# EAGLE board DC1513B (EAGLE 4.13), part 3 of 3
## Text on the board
Top: 4
L2-GND: LAYER 2, GND | 5
Route3: LAYER 3, GND | 6
Bottom: 7
tPlace: PIN A1> | 2
bPlace: 9
tNames: +5.0V | GND | GND | +3.0V | ON | ON | ON | ON | ON | 2/3 | VDD | MIXER | OFF | OFF | SDI | SDQ | OFF | OFF | SDI | SDQ | OFF | MODE | SENSE_I | 1/3 | GND | AMPS | ADC | VIOB | SENSE_B | GND | GND | LTM9004 | DC1513B- | OVDD | 14BIT BIT DIRECT CONVERSION | RECEIVER SUBSYSEM DEMO BOARD | J6 | LO IN | Q OFFSET | I OFFSET | RF IN | (408)432-1900 | WR_EN | www.linear.com | ENCODE | CLOCK
bNames: LTC CONFIDENTIAL | FOR CUSTOMER USE ONLY
tStop: 3
bStop: 8
tCream: 1
bCream: 10
bRestrict: BACK | REV B1
Measures: 2.950 IN | 0.652 | 0.050 IN | 0 | ORIGIN | 0.967 IN | 0.067 IN TOOLING HOLE | 0 | UNPLATED, 2X | 0.050 IN | 3.660 IN | 1.0575
Document: LTM9004 DEMO BOARD | DC1513 | 14BIT BIT DIRECT CONVERSION RCVR SUBSYS | B | 10 | E.TRELEWICZ | 28JSEP09
Reference: A1 | INITIAL RELEASE | 28JAN09 | B1 | VCC3 SUPPLY OPTION | 28SEP09 | 1 | 0.009" | 1 | 0.039" | 1 | 0.009" | 1 | VIEW A | HERE | NO TABS | DC1513 REV B | HERE | NO TABS | HERE | NO TABS | DRILL LEGEND | SYM SIZE QTY TOLERANCE PLTD | .010 | 245 | +0/-.010 | YES | .012 | 70 | +0/- .012 | YES | 994 | .015 | +/- .003 | YES | .020 | 0 | +/- .003 | YES | .032 | 32 | +/- .003 | YES | E.TRELEWICZ | 28JAN09 | LTM9004 DEMO BOARD | .066 | 7 | +/- .003 | YES | .067 | 2 | +.004/-0 | NO | 14BIT BIT DIRECT CONVERSION RCVR SUBSYSTEM | .080 | 0 | +.003/-0 | NO | E.TRELEWICZ | 28JAN09 | .125 | 0 | +/- .003 | NO | .188 | 4 | +/- .003 | YES | E.TRELEWICZ | 28JAN09 | DC1513 | A | B | 1 | 1
tDocu: PIN A1> | LTM9004 DEMO BOARD | DC1513 | 14BIT BIT DIRECT CONVERSION RCVR SUBSYS | B | E.TRELEWICZ | 28SEP09
bDocu: J7 | LTM9004 SOCKETED TEST BOARD | DC1513 | 14BIT BIT DIRECT CONVERSION RCVR SUBSYS | B | E.TRELEWICZ | 28FEB09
